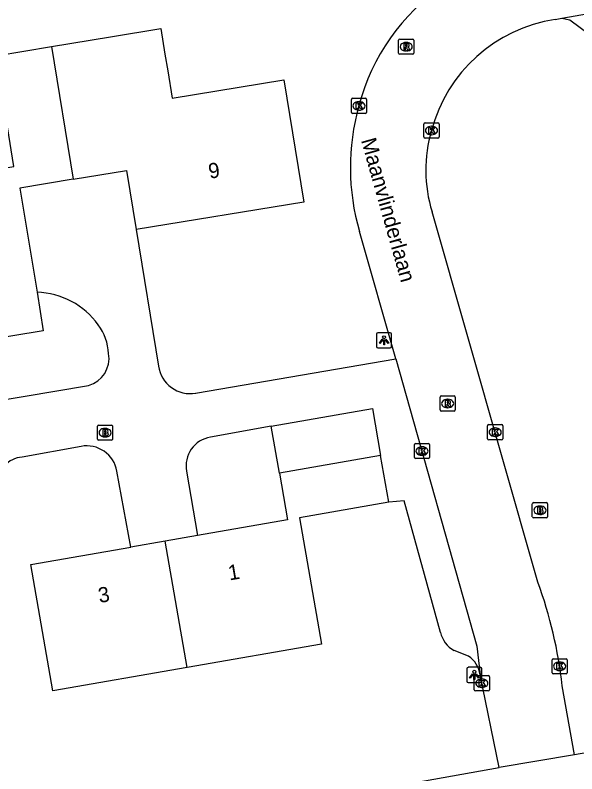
# Model space of a CAD drawing. Extents: x 162880 to 165536, y 384011 to 385179.
# Drawn here: x 163883.7 to 163920.7, y 384694 to 384744.1 of the extents above; entities that cross this region are included whole.
import ezdxf

# ---------------------------------------------------------------- set-up
doc = ezdxf.new("R2010")
doc.units = 0
for name, color, linetype in [('IMGEO_Brandkraan', 7, 'Continuous'), ('IMGEO_Kolk', 7, 'Continuous'), ('IMGEO_Lichtpunt', 7, 'Continuous'), ('IMGEO_Openbare_ruimte_label', 7, 'Continuous'), ('IMGEO_Pand', 7, 'Continuous'), ('IMGEO_Pand_nummerreeks', 7, 'Continuous'), ('IMGEO_Rijbaan_lokaal_open', 7, 'Continuous'), ('IMGEO_Rioolput', 7, 'Continuous'), ('IMGEO_Voetpad_open', 7, 'Continuous')]:
    doc.layers.add(name, color=color, linetype=linetype)

msp = doc.modelspace()

# ---------------------------------------------------------------- linework, layer by layer
at = {"layer": 'IMGEO_Brandkraan'}
for p, q in [((163889.089, 384716.1), (163889.089, 384716.952)), ((163889.164, 384717.026), (163890.016, 384717.026)), ((163889.577, 384716.806), (163889.602, 384716.806)), ((163890.09, 384716.952), (163890.09, 384716.1)), ((163890.016, 384716.026), (163889.164, 384716.026)), ((163889.6, 384716.246), (163889.575, 384716.246)), ((163917.779, 384710.984), (163917.779, 384711.836)), ((163917.854, 384711.91), (163918.706, 384711.91)), ((163918.78, 384711.836), (163918.78, 384710.984)), ((163918.267, 384711.69), (163918.292, 384711.69)), ((163918.706, 384710.91), (163917.854, 384710.91)), ((163918.29, 384711.13), (163918.265, 384711.13))]:
    msp.add_line(p, q, dxfattribs=at)
for points in [[(163889.089, 384716.1), (163889.089, 384716.952)], [(163889.164, 384717.026), (163890.016, 384717.026)], [(163890.09, 384716.952), (163890.09, 384716.1)], [(163889.437, 384716.726), (163889.437, 384716.326), (163889.65, 384716.326)], [(163889.668, 384716.726), (163889.437, 384716.726)], [(163889.616, 384716.645), (163889.562, 384716.645), (163889.562, 384716.569)], [(163889.562, 384716.569), (163889.615, 384716.569)], [(163889.624, 384716.493), (163889.562, 384716.493), (163889.562, 384716.412)], [(163889.562, 384716.412), (163889.624, 384716.412)], [(163890.016, 384716.026), (163889.164, 384716.026)], [(163917.779, 384710.984), (163917.779, 384711.836)], [(163917.854, 384711.91), (163918.706, 384711.91)], [(163918.78, 384711.836), (163918.78, 384710.984)], [(163918.127, 384711.61), (163918.127, 384711.21), (163918.34, 384711.21)], [(163918.358, 384711.61), (163918.127, 384711.61)], [(163918.306, 384711.529), (163918.252, 384711.529), (163918.252, 384711.453)], [(163918.252, 384711.453), (163918.305, 384711.453)], [(163918.314, 384711.377), (163918.252, 384711.377), (163918.252, 384711.296)], [(163918.252, 384711.296), (163918.314, 384711.296)], [(163918.706, 384710.91), (163917.854, 384710.91)]]:
    msp.add_lwpolyline(points, dxfattribs=at)
for centre, radius, start, end in [((163889.166, 384716.95), 0.0765, 91.552, 178.448), ((163889.166, 384716.95), 0.0765, 91.552, 178.448), ((163890.014, 384716.95), 0.0765, 1.552, 88.448), ((163890.014, 384716.95), 0.0765, 1.552, 88.448), ((163889.617, 384716.607), 0.0379, 267.8285, 90.9355), ((163889.625, 384716.452), 0.0404, 269.8759, 90.5077), ((163889.656, 384716.577), 0.251, 268.6676, 293.5347), ((163889.672, 384716.581), 0.145, 59.4692, 91.5367), ((163889.697, 384716.628), 0.0922, 285.5137, 58.1501), ((163889.702, 384716.436), 0.105, 301.3115, 78.989), ((163889.166, 384716.102), 0.0765, 181.552, 268.448), ((163889.166, 384716.102), 0.0765, 181.552, 268.448), ((163890.014, 384716.102), 0.0765, 271.552, 358.448), ((163890.014, 384716.102), 0.0765, 271.552, 358.448), ((163917.856, 384711.834), 0.0765, 91.552, 178.448), ((163917.856, 384711.834), 0.0765, 91.552, 178.448), ((163918.704, 384711.834), 0.0765, 1.552, 88.448), ((163918.704, 384711.834), 0.0765, 1.552, 88.448), ((163918.307, 384711.491), 0.0379, 267.8285, 90.9355), ((163918.315, 384711.336), 0.0404, 269.8759, 90.5077), ((163918.362, 384711.465), 0.145, 59.4692, 91.5367), ((163918.387, 384711.512), 0.0922, 285.5137, 58.1501), ((163918.392, 384711.32), 0.105, 301.3115, 78.989), ((163917.856, 384710.986), 0.0765, 181.552, 268.448), ((163917.856, 384710.986), 0.0765, 181.552, 268.448), ((163918.346, 384711.461), 0.251, 268.6676, 293.5347), ((163918.704, 384710.986), 0.0765, 271.552, 358.448), ((163918.704, 384710.986), 0.0765, 271.552, 358.448)]:
    msp.add_arc(centre, radius, start, end, dxfattribs=at)
for centre, major_axis, ratio, start_param, end_param in [((163889.576, 384716.526), (-0.387, 0.002), 0.722429, 4.712389, 7.853982), ((163889.601, 384716.526), (-0.39, 0.002), 0.717154, 1.570796, 4.712389), ((163918.266, 384711.41), (-0.387, 0.002), 0.722429, 4.712389, 7.853982), ((163918.291, 384711.41), (-0.39, 0.002), 0.717154, 1.570796, 4.712389)]:
    msp.add_ellipse(centre, major_axis=major_axis, ratio=ratio, start_param=start_param, end_param=end_param, dxfattribs=at)
at = {"layer": 'IMGEO_Kolk'}
for p, q in [((163905.838, 384737.651), (163905.838, 384738.503)), ((163905.913, 384738.577), (163906.765, 384738.577)), ((163906.326, 384738.357), (163906.351, 384738.357)), ((163906.839, 384738.503), (163906.839, 384737.651)), ((163906.349, 384737.797), (163906.324, 384737.797)), ((163906.765, 384737.577), (163905.913, 384737.577)), ((163910.624, 384736.03), (163910.624, 384736.882)), ((163910.699, 384736.956), (163911.551, 384736.956)), ((163911.625, 384736.882), (163911.625, 384736.03)), ((163911.112, 384736.736), (163911.137, 384736.736)), ((163911.551, 384735.956), (163910.699, 384735.956)), ((163911.135, 384736.176), (163911.11, 384736.176)), ((163914.824, 384716.129), (163914.824, 384716.981)), ((163914.899, 384717.055), (163915.751, 384717.055)), ((163915.312, 384716.835), (163915.337, 384716.835)), ((163915.825, 384716.981), (163915.825, 384716.129)), ((163915.335, 384716.275), (163915.31, 384716.275)), ((163910.073, 384715.812), (163910.925, 384715.812)), ((163915.751, 384716.055), (163914.899, 384716.055)), ((163909.998, 384714.886), (163909.998, 384715.738)), ((163910.486, 384715.592), (163910.511, 384715.592)), ((163910.999, 384715.738), (163910.999, 384714.886)), ((163910.925, 384714.812), (163910.073, 384714.812)), ((163910.509, 384715.032), (163910.484, 384715.032)), ((163919.077, 384700.694), (163919.077, 384701.546)), ((163919.152, 384701.62), (163920.004, 384701.62)), ((163919.565, 384701.4), (163919.59, 384701.4)), ((163920.078, 384701.546), (163920.078, 384700.694)), ((163919.588, 384700.84), (163919.563, 384700.84)), ((163913.945, 384699.577), (163913.945, 384700.429)), ((163914.02, 384700.503), (163914.872, 384700.503)), ((163914.433, 384700.283), (163914.458, 384700.283)), ((163914.946, 384700.429), (163914.946, 384699.577)), ((163920.004, 384700.62), (163919.152, 384700.62)), ((163914.872, 384699.503), (163914.02, 384699.503)), ((163914.456, 384699.723), (163914.431, 384699.723))]:
    msp.add_line(p, q, dxfattribs=at)
for points in [[(163905.838, 384737.651), (163905.838, 384738.503)], [(163905.913, 384738.577), (163906.765, 384738.577)], [(163906.839, 384738.503), (163906.839, 384737.651)], [(163906.159, 384738.277), (163906.282, 384738.277), (163906.282, 384738.126), (163906.412, 384738.277), (163906.576, 384738.277), (163906.43, 384738.126), (163906.583, 384737.877), (163906.431, 384737.877), (163906.346, 384738.041), (163906.282, 384737.974), (163906.282, 384737.877), (163906.159, 384737.877), (163906.159, 384738.277)], [(163906.765, 384737.577), (163905.913, 384737.577)], [(163910.624, 384736.03), (163910.624, 384736.882)], [(163910.699, 384736.956), (163911.551, 384736.956)], [(163911.625, 384736.882), (163911.625, 384736.03)], [(163910.945, 384736.656), (163911.068, 384736.656), (163911.068, 384736.505), (163911.198, 384736.656), (163911.362, 384736.656), (163911.216, 384736.505), (163911.369, 384736.256), (163911.217, 384736.256), (163911.132, 384736.42), (163911.068, 384736.353), (163911.068, 384736.256), (163910.945, 384736.256), (163910.945, 384736.656)], [(163911.551, 384735.956), (163910.699, 384735.956)], [(163914.824, 384716.129), (163914.824, 384716.981)], [(163914.899, 384717.055), (163915.751, 384717.055)], [(163915.825, 384716.981), (163915.825, 384716.129)], [(163915.145, 384716.755), (163915.268, 384716.755), (163915.268, 384716.604), (163915.398, 384716.755), (163915.562, 384716.755), (163915.416, 384716.604), (163915.569, 384716.355), (163915.417, 384716.355), (163915.332, 384716.519), (163915.268, 384716.452), (163915.268, 384716.355), (163915.145, 384716.355), (163915.145, 384716.755)], [(163910.073, 384715.812), (163910.925, 384715.812)], [(163915.751, 384716.055), (163914.899, 384716.055)], [(163909.998, 384714.886), (163909.998, 384715.738)], [(163910.319, 384715.512), (163910.442, 384715.512), (163910.442, 384715.361), (163910.572, 384715.512), (163910.736, 384715.512), (163910.59, 384715.361), (163910.743, 384715.112), (163910.591, 384715.112), (163910.506, 384715.276), (163910.442, 384715.209), (163910.442, 384715.112), (163910.319, 384715.112), (163910.319, 384715.512)], [(163910.999, 384715.738), (163910.999, 384714.886)], [(163910.925, 384714.812), (163910.073, 384714.812)], [(163919.077, 384700.694), (163919.077, 384701.546)], [(163919.152, 384701.62), (163920.004, 384701.62)], [(163919.398, 384701.32), (163919.521, 384701.32), (163919.521, 384701.169), (163919.651, 384701.32), (163919.815, 384701.32), (163919.669, 384701.169), (163919.822, 384700.92), (163919.67, 384700.92), (163919.585, 384701.084), (163919.521, 384701.017), (163919.521, 384700.92), (163919.398, 384700.92), (163919.398, 384701.32)], [(163920.078, 384701.546), (163920.078, 384700.694)], [(163913.945, 384699.577), (163913.945, 384700.429)], [(163914.02, 384700.503), (163914.872, 384700.503)], [(163914.946, 384700.429), (163914.946, 384699.577)], [(163920.004, 384700.62), (163919.152, 384700.62)], [(163914.266, 384700.203), (163914.389, 384700.203), (163914.389, 384700.052), (163914.519, 384700.203), (163914.683, 384700.203), (163914.537, 384700.052), (163914.69, 384699.803), (163914.538, 384699.803), (163914.453, 384699.967), (163914.389, 384699.9), (163914.389, 384699.803), (163914.266, 384699.803), (163914.266, 384700.203)], [(163914.872, 384699.503), (163914.02, 384699.503)]]:
    msp.add_lwpolyline(points, dxfattribs=at)
for centre, start, end in [((163905.915, 384738.501), 91.552, 178.448), ((163905.915, 384738.501), 91.552, 178.448), ((163906.763, 384738.501), 1.552, 88.448), ((163906.763, 384738.501), 1.552, 88.448), ((163905.915, 384737.653), 181.552, 268.448), ((163905.915, 384737.653), 181.552, 268.448), ((163906.763, 384737.653), 271.552, 358.448), ((163906.763, 384737.653), 271.552, 358.448), ((163910.701, 384736.88), 91.552, 178.448), ((163910.701, 384736.88), 91.552, 178.448), ((163911.549, 384736.88), 1.552, 88.448), ((163911.549, 384736.88), 1.552, 88.448), ((163910.701, 384736.032), 181.552, 268.448), ((163910.701, 384736.032), 181.552, 268.448), ((163911.549, 384736.032), 271.552, 358.448), ((163911.549, 384736.032), 271.552, 358.448), ((163914.901, 384716.979), 91.552, 178.448), ((163914.901, 384716.979), 91.552, 178.448), ((163915.749, 384716.979), 1.552, 88.448), ((163915.749, 384716.979), 1.552, 88.448), ((163910.075, 384715.736), 91.552, 178.448), ((163910.075, 384715.736), 91.552, 178.448), ((163910.923, 384715.736), 1.552, 88.448), ((163910.923, 384715.736), 1.552, 88.448), ((163914.901, 384716.131), 181.552, 268.448), ((163914.901, 384716.131), 181.552, 268.448), ((163915.749, 384716.131), 271.552, 358.448), ((163915.749, 384716.131), 271.552, 358.448), ((163910.075, 384714.888), 181.552, 268.448), ((163910.075, 384714.888), 181.552, 268.448), ((163910.923, 384714.888), 271.552, 358.448), ((163910.923, 384714.888), 271.552, 358.448), ((163919.154, 384701.544), 91.552, 178.448), ((163919.154, 384701.544), 91.552, 178.448), ((163920.002, 384701.544), 1.552, 88.448), ((163920.002, 384701.544), 1.552, 88.448), ((163914.022, 384700.427), 91.552, 178.448), ((163914.022, 384700.427), 91.552, 178.448), ((163914.87, 384700.427), 1.552, 88.448), ((163914.87, 384700.427), 1.552, 88.448), ((163919.154, 384700.696), 181.552, 268.448), ((163919.154, 384700.696), 181.552, 268.448), ((163920.002, 384700.696), 271.552, 358.448), ((163920.002, 384700.696), 271.552, 358.448), ((163914.022, 384699.579), 181.552, 268.448), ((163914.022, 384699.579), 181.552, 268.448), ((163914.87, 384699.579), 271.552, 358.448), ((163914.87, 384699.579), 271.552, 358.448)]:
    msp.add_arc(centre, 0.0765, start, end, dxfattribs=at)
for centre, major_axis, ratio, start_param, end_param in [((163906.325, 384738.077), (-0.387, 0.002), 0.722429, 4.712389, 7.853982), ((163906.35, 384738.077), (-0.39, 0.002), 0.717154, 1.570796, 4.712389), ((163911.111, 384736.456), (-0.387, 0.002), 0.722429, 4.712389, 7.853982), ((163911.136, 384736.456), (-0.39, 0.002), 0.717154, 1.570796, 4.712389), ((163915.311, 384716.555), (-0.387, 0.002), 0.722429, 4.712389, 7.853982), ((163915.336, 384716.555), (-0.39, 0.002), 0.717154, 1.570796, 4.712389), ((163910.485, 384715.312), (-0.387, 0.002), 0.722429, 4.712389, 7.853982), ((163910.51, 384715.312), (-0.39, 0.002), 0.717154, 1.570796, 4.712389), ((163919.564, 384701.12), (-0.387, 0.002), 0.722429, 4.712389, 7.853982), ((163919.589, 384701.12), (-0.39, 0.002), 0.717154, 1.570796, 4.712389), ((163914.432, 384700.003), (-0.387, 0.002), 0.722429, 4.712389, 7.853982), ((163914.457, 384700.003), (-0.39, 0.002), 0.717154, 1.570796, 4.712389)]:
    msp.add_ellipse(centre, major_axis=major_axis, ratio=ratio, start_param=start_param, end_param=end_param, dxfattribs=at)
at = {"layer": 'IMGEO_Lichtpunt'}
for p, q in [((163907.5, 384723.024), (163907.5, 384722.217)), ((163907.5, 384723.024), (163907.5, 384722.217)), ((163908.402, 384723.119), (163907.594, 384723.119)), ((163908.402, 384723.119), (163907.594, 384723.119)), ((163908.496, 384722.217), (163908.496, 384723.024)), ((163908.496, 384722.217), (163908.496, 384723.024)), ((163907.594, 384722.123), (163908.402, 384722.123)), ((163907.594, 384722.123), (163908.402, 384722.123)), ((163913.452, 384700.955), (163913.452, 384700.148)), ((163913.452, 384700.955), (163913.452, 384700.148)), ((163914.354, 384701.05), (163913.546, 384701.05)), ((163914.354, 384701.05), (163913.546, 384701.05)), ((163914.448, 384700.148), (163914.448, 384700.955)), ((163914.448, 384700.148), (163914.448, 384700.955)), ((163913.546, 384700.054), (163914.354, 384700.054)), ((163913.546, 384700.054), (163914.354, 384700.054))]:
    msp.add_line(p, q, dxfattribs=at)
for points in [[(163907.874, 384722.688), (163907.913, 384722.66), (163907.725, 384722.398), (163907.687, 384722.425), (163907.874, 384722.688)], [(163907.976, 384722.64), (163908.023, 384722.64), (163908.023, 384722.318), (163907.976, 384722.318), (163907.976, 384722.64)], [(163908.086, 384722.66), (163908.124, 384722.687), (163908.311, 384722.425), (163908.272, 384722.397), (163908.086, 384722.66)], [(163913.826, 384700.619), (163913.865, 384700.591), (163913.677, 384700.329), (163913.639, 384700.356), (163913.826, 384700.619)], [(163913.928, 384700.571), (163913.975, 384700.571), (163913.975, 384700.249), (163913.928, 384700.249), (163913.928, 384700.571)], [(163914.038, 384700.591), (163914.076, 384700.618), (163914.263, 384700.356), (163914.224, 384700.328), (163914.038, 384700.591)]]:
    msp.add_lwpolyline(points, dxfattribs=at)
for centre in [(163907.999, 384722.822), (163913.951, 384700.753)]:
    msp.add_circle(centre, 0.0994, dxfattribs=at)
for centre, start, end in [((163907.594, 384723.024), 90, 180), ((163907.594, 384723.024), 90, 180), ((163908.402, 384723.024), 0, 90), ((163908.402, 384723.024), 0, 90), ((163907.594, 384722.217), 180, 270), ((163907.594, 384722.217), 180, 270), ((163908.402, 384722.217), 270, 0), ((163908.402, 384722.217), 270, 360), ((163913.546, 384700.955), 90, 180), ((163913.546, 384700.955), 90, 180), ((163914.354, 384700.955), 0, 90), ((163914.354, 384700.955), 0, 90), ((163913.546, 384700.148), 180, 270), ((163913.546, 384700.148), 180, 270), ((163914.354, 384700.148), 270, 0), ((163914.354, 384700.148), 270, 360)]:
    msp.add_arc(centre, 0.0946, start, end, dxfattribs=at)
at = {"layer": 'IMGEO_Pand'}
for points in [[(163886.053, 384741.989), (163889.955, 384742.63), (163893.266, 384743.173), (163893.542, 384741.496), (163893.722, 384740.393), (163894.02, 384738.577), (163901.381, 384739.786), (163902.704, 384731.735), (163891.639, 384729.918)], [(163885.098, 384725.784), (163885.515, 384723.247), (163877.611, 384721.948), (163876.918, 384726.168), (163873.726, 384725.644), (163872.96, 384730.309), (163876.152, 384730.834), (163875.828, 384732.804), (163883.571, 384734.075), (163882.371, 384741.385), (163886.053, 384741.989)], [(163886.053, 384741.989), (163887.485, 384733.235)], [(163887.485, 384733.235), (163891, 384733.812), (163891.639, 384729.918)], [(163887.485, 384733.235), (163883.97, 384732.658), (163885.098, 384725.784)], [(163900.557, 384716.957), (163907.234, 384718.113), (163907.772, 384715.011)], [(163901.095, 384713.852), (163900.557, 384716.957)], [(163907.772, 384715.011), (163901.095, 384713.852)], [(163908.305, 384711.934), (163907.772, 384715.011)], [(163901.095, 384713.852), (163901.629, 384710.769), (163895.696, 384709.741)], [(163908.305, 384711.934), (163902.428, 384710.916), (163903.874, 384702.568), (163895.01, 384701.032)], [(163893.564, 384709.372), (163891.298, 384708.979)], [(163895.696, 384709.741), (163893.564, 384709.372)], [(163895.01, 384701.032), (163893.564, 384709.372)], [(163895.01, 384701.032), (163886.147, 384699.496), (163884.702, 384707.836), (163891.298, 384708.979)]]:
    msp.add_lwpolyline(points, dxfattribs=at)
at = {"layer": 'IMGEO_Rijbaan_lokaal_open'}
for points in [[(163919.73, 384743.856), (163927.644, 384745.267), (163930.393, 384745.609), (163929.752, 384750), (163929.624, 384750.664)], [(163919.284, 384743.776), (163919.73, 384743.856)], [(163918.145, 384706.657), (163911.164, 384731.1)], [(163891.639, 384729.918), (163893.115, 384720.915)], [(163908.767, 384721.4), (163906.373, 384729.786)], [(163895.566, 384719.132), (163908.767, 384721.4)], [(163908.767, 384721.4), (163914.109, 384702.441), (163914.34, 384700.546)], [(163879.99, 384718.206), (163888.503, 384719.643)], [(163900.557, 384716.957), (163896.539, 384716.219)], [(163888.005, 384715.624), (163884.11, 384714.914)], [(163891.298, 384708.979), (163890.373, 384713.987)], [(163894.971, 384713.984), (163895.696, 384709.741)], [(163911.724, 384703.356), (163909.328, 384712.027), (163908.305, 384711.934)], [(163913.562, 384701.796), (163912.611, 384702.161)], [(163915.582, 384694.452), (163914.34, 384700.546)], [(163920.553, 384695.282), (163919.751, 384699.84)], [(163920.553, 384695.282), (163915.582, 384694.452)]]:
    msp.add_lwpolyline(points, dxfattribs=at)
for centre, radius, start, end in [((163919.658, 384734.639), 13.757, 124.1575, 165.5252), ((163920.767, 384733.918), 9.969, 98.5525, 165.2572), ((163920.79, 384733.992), 15.018, 164.2178, 196.2659), ((163919.976, 384733.84), 9.228, 163.5388, 197.2744), ((163884.947, 384720.624), 5.162, 35.6414, 88.3196), ((163886.254, 384721.526), 3.574, 3.3982, 36.101), ((163887.994, 384721.426), 1.855, 285.9432, 9.6683), ((163895.211, 384721.219), 2.118, 188.2674, 279.6639), ((163896.816, 384714.357), 1.883, 98.4681, 191.4275), ((163888.373, 384713.626), 2.032, 10.2467, 100.441), ((163884.186, 384713.363), 1.553, 92.8049, 141.9519), ((163890.721, 384696.598), 29.211, 6.3712, 20.1417), ((163913.472, 384703.727), 1.787, 191.976, 241.194), ((163912.537, 384700.291), 1.821, 8.0593, 55.737)]:
    msp.add_arc(centre, radius, start, end, dxfattribs=at)
at = {"layer": 'IMGEO_Rioolput'}
for p, q in [((163908.958, 384741.554), (163908.958, 384742.406)), ((163909.033, 384742.48), (163909.885, 384742.48)), ((163909.959, 384742.406), (163909.959, 384741.554)), ((163909.446, 384742.26), (163909.471, 384742.26)), ((163909.885, 384741.48), (163909.033, 384741.48)), ((163909.469, 384741.7), (163909.444, 384741.7)), ((163911.689, 384718.024), (163911.689, 384718.876)), ((163911.764, 384718.95), (163912.616, 384718.95)), ((163912.69, 384718.876), (163912.69, 384718.024)), ((163912.177, 384718.73), (163912.202, 384718.73)), ((163912.616, 384717.95), (163911.764, 384717.95)), ((163912.2, 384718.17), (163912.175, 384718.17))]:
    msp.add_line(p, q, dxfattribs=at)
for points in [[(163908.958, 384741.554), (163908.958, 384742.406)], [(163909.033, 384742.48), (163909.885, 384742.48)], [(163909.959, 384742.406), (163909.959, 384741.554)], [(163909.547, 384742.178), (163909.295, 384742.18), (163909.295, 384741.78)], [(163909.295, 384741.78), (163909.419, 384741.78), (163909.419, 384741.942), (163909.43, 384741.942)], [(163909.473, 384742.099), (163909.419, 384742.099), (163909.419, 384742.018)], [(163909.419, 384742.018), (163909.471, 384742.018)], [(163909.477, 384741.913), (163909.548, 384741.78), (163909.688, 384741.78), (163909.623, 384741.906)], [(163909.885, 384741.48), (163909.033, 384741.48)], [(163911.689, 384718.024), (163911.689, 384718.876)], [(163911.764, 384718.95), (163912.616, 384718.95)], [(163912.69, 384718.876), (163912.69, 384718.024)], [(163912.278, 384718.648), (163912.026, 384718.65), (163912.026, 384718.25)], [(163912.026, 384718.25), (163912.15, 384718.25), (163912.15, 384718.412), (163912.161, 384718.412)], [(163912.204, 384718.569), (163912.15, 384718.569), (163912.15, 384718.488)], [(163912.15, 384718.488), (163912.202, 384718.488)], [(163912.208, 384718.383), (163912.279, 384718.25), (163912.419, 384718.25), (163912.354, 384718.376)], [(163912.616, 384717.95), (163911.764, 384717.95)]]:
    msp.add_lwpolyline(points, dxfattribs=at)
for centre, radius, start, end in [((163909.035, 384742.404), 0.0765, 91.552, 178.448), ((163909.035, 384742.404), 0.0765, 91.552, 178.448), ((163909.883, 384742.404), 0.0765, 1.552, 88.448), ((163909.883, 384742.404), 0.0765, 1.552, 88.448), ((163909.429, 384741.889), 0.0533, 26.0293, 88.6989), ((163909.455, 384742.207), 0.19, 274.7715, 282.9687), ((163909.479, 384742.003), 0.0964, 77.0061, 93.1865), ((163909.493, 384742.06), 0.0378, 276.6634, 79.6772), ((163909.546, 384742.068), 0.109, 350.3612, 89.416), ((163909.544, 384742.068), 0.112, 277.5842, 350.9817), ((163909.528, 384741.853), 0.108, 29.5134, 73.7905), ((163909.035, 384741.556), 0.0765, 181.552, 268.448), ((163909.035, 384741.556), 0.0765, 181.552, 268.448), ((163909.883, 384741.556), 0.0765, 271.552, 358.448), ((163909.883, 384741.556), 0.0765, 271.552, 358.448), ((163911.766, 384718.874), 0.0765, 91.552, 178.448), ((163911.766, 384718.874), 0.0765, 91.552, 178.448), ((163912.614, 384718.874), 0.0765, 1.552, 88.448), ((163912.614, 384718.874), 0.0765, 1.552, 88.448), ((163912.16, 384718.359), 0.0533, 26.0293, 88.6989), ((163912.186, 384718.677), 0.19, 274.7715, 282.9687), ((163912.21, 384718.473), 0.0964, 77.0061, 93.1865), ((163912.224, 384718.53), 0.0378, 276.6634, 79.6772), ((163912.277, 384718.538), 0.109, 350.3612, 89.416), ((163912.275, 384718.538), 0.112, 277.5842, 350.9817), ((163912.259, 384718.323), 0.108, 29.5134, 73.7905), ((163911.766, 384718.026), 0.0765, 181.552, 268.448), ((163911.766, 384718.026), 0.0765, 181.552, 268.448), ((163912.614, 384718.026), 0.0765, 271.552, 358.448), ((163912.614, 384718.026), 0.0765, 271.552, 358.448)]:
    msp.add_arc(centre, radius, start, end, dxfattribs=at)
for centre, major_axis, ratio, start_param, end_param in [((163909.445, 384741.98), (-0.387, 0.002), 0.722429, 4.712389, 7.853982), ((163909.47, 384741.98), (-0.39, 0.002), 0.717154, 1.570796, 4.712389), ((163912.176, 384718.45), (-0.387, 0.002), 0.722429, 4.712389, 7.853982), ((163912.201, 384718.45), (-0.39, 0.002), 0.717154, 1.570796, 4.712389)]:
    msp.add_ellipse(centre, major_axis=major_axis, ratio=ratio, start_param=start_param, end_param=end_param, dxfattribs=at)
at = {"layer": 'IMGEO_Voetpad_open'}
for points in [[(163919.73, 384743.856), (163920.259, 384743.743), (163921.62, 384742.749)], [(163986.591, 384706.78), (163920.553, 384695.282)], [(163886.647, 384689.276), (163915.582, 384694.452)]]:
    msp.add_lwpolyline(points, dxfattribs=at)

# ---------------------------------------------------------------- texts
at = {"layer": 'IMGEO_Openbare_ruimte_label'}
msp.add_text('Maanvlinderlaan', height=1, rotation=285.7328, dxfattribs=at).set_placement((163906.47, 384735.813))
at = {"layer": 'IMGEO_Pand_nummerreeks'}
for s, rotation, p in [('9', 9.3278, (163896.491, 384733.269)), ('1', 9.8302, (163897.798, 384706.776)), ('3', 9.8302, (163889.222, 384705.29))]:
    msp.add_text(s, height=1, rotation=rotation, dxfattribs=at).set_placement(p)

doc.saveas('drawing.dxf')
